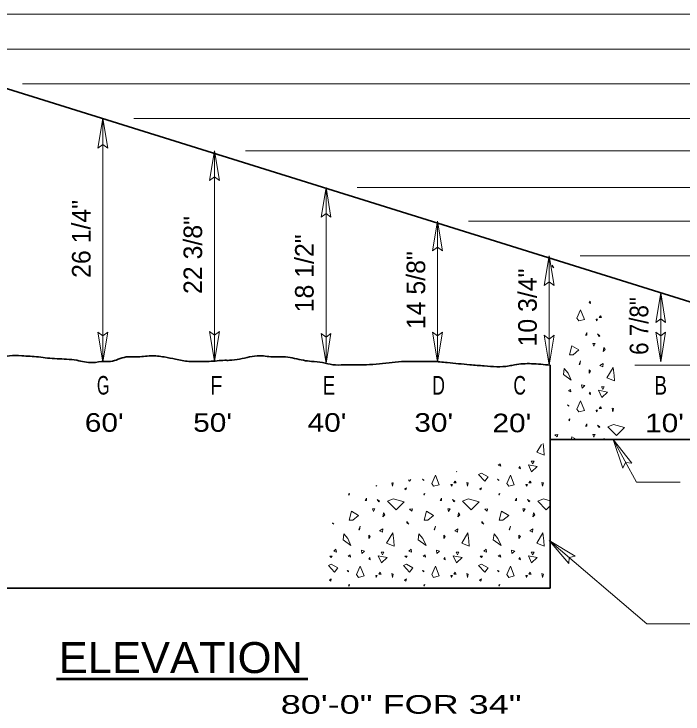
# Model space of a CAD drawing. Extents: x -15.1 to -7.9, y 13.6 to 23.8.
# Drawn here: x -13.723 to -11.564, y 19.638 to 21.898 of the extents above; entities that cross this region are included whole.
import ezdxf
from ezdxf.enums import TextEntityAlignment as Align

# ---------------------------------------------------------------- set-up
doc = ezdxf.new("R2010")
doc.units = 0
doc.header["$LTSCALE"] = 0.024
for name, color, linetype, lineweight in [('1', 7, 'Continuous', 35), ('10', 7, 'Continuous', 13), ('12', 7, 'Continuous', 53), ('6', 7, 'Continuous', 13)]:
    doc.layers.add(name, color=color, linetype=linetype, lineweight=lineweight)

msp = doc.modelspace()

# ---------------------------------------------------------------- linework, layer by layer
at = {"layer": '1'}
for p, q in [((-14.51633, 21.89767), (-11.27283, 20.88417)), ((-11.993, 20.044), (-11.993, 20.7645)), ((-11.993, 20.044), (-14.91633, 20.044))]:
    msp.add_line(p, q, dxfattribs=at)
msp.add_lwpolyline([(-11.993, 20.524), (-11.27283, 20.524), (-11.27283, 20.88417)], dxfattribs=at)
msp.add_spline([(-11.993, 20.76417), (-12.053, 20.769), (-12.1075, 20.7655), (-12.1255, 20.76183), (-12.20533, 20.76183), (-12.25233, 20.7655), (-12.32483, 20.77267), (-12.372, 20.77633), (-12.41917, 20.77633), (-12.46267, 20.77633), (-12.5025, 20.77267), (-12.58583, 20.7655), (-12.6185, 20.7655), (-12.65833, 20.7655), (-12.6945, 20.7655), (-12.72717, 20.77267), (-12.7635, 20.77633), (-12.78883, 20.77983), (-12.84683, 20.79067), (-12.883, 20.79067), (-12.93017, 20.79433), (-12.96283, 20.79067), (-13.028, 20.77983), (-13.0425, 20.77983), (-13.09317, 20.77633), (-13.11867, 20.77633), (-13.1585, 20.77633), (-13.202, 20.7835), (-13.23817, 20.79067), (-13.28167, 20.79433), (-13.32883, 20.79067), (-13.3615, 20.79067), (-13.41217, 20.77633), (-13.43033, 20.77633), (-13.47017, 20.77267), (-13.52083, 20.77983), (-13.5535, 20.7835), (-13.61517, 20.78717), (-13.64417, 20.79067), (-13.6985, 20.79433), (-13.73833, 20.79433), (-13.8, 20.77983), (-13.81083, 20.77983), (-13.84717, 20.77983), (-13.90517, 20.7835), (-13.974, 20.7835), (-14.01383, 20.77983), (-14.05733, 20.769), (-14.0935, 20.75817), (-14.108, 20.75467), (-14.14067, 20.75467), (-14.17333, 20.75467), (-14.23483, 20.76183), (-14.27483, 20.76183), (-14.31833, 20.75817), (-14.34717, 20.75467), (-14.369, 20.75467), (-14.40883, 20.75467), (-14.43783, 20.75817), (-14.456, 20.7655), (-14.46683, 20.769), (-14.48867, 20.77633), (-14.50317, 20.77633), (-14.51033, 20.77633)], degree=3, dxfattribs=at)
at = {"layer": '10'}
for p, q in [((-14.41633, 21.89767), (-9.09375, 21.89767)), ((-14.05633, 21.78433), (-9.13367, 21.78433)), ((-13.69633, 21.67267), (-9.14125, 21.67267)), ((-13.45233, 21.46417), (-13.43633, 21.56017)), ((-13.43633, 20.775), (-13.43633, 21.56017)), ((-13.42033, 21.46417), (-13.43633, 21.56017)), ((-13.33633, 21.56017), (-9.14125, 21.56017)), ((-13.45233, 21.46417), (-13.43633, 21.47617)), ((-13.42033, 21.46417), (-13.43633, 21.47617)), ((-13.09217, 21.36017), (-13.07617, 21.45617)), ((-13.06017, 21.36017), (-13.07617, 21.45617)), ((-13.07617, 20.777), (-13.07617, 21.45617)), ((-12.97617, 21.45617), (-9.14125, 21.45617)), ((-13.09217, 21.36017), (-13.07617, 21.37217)), ((-13.06017, 21.36017), (-13.07617, 21.37217)), ((-12.73217, 21.24167), (-12.71617, 21.33767)), ((-12.70017, 21.24167), (-12.71617, 21.33767)), ((-12.71617, 20.77017), (-12.71617, 21.33767)), ((-12.61617, 21.33767), (-9.14883, 21.33767)), ((-12.73217, 21.24167), (-12.71617, 21.25367)), ((-12.70017, 21.24167), (-12.71617, 21.25367)), ((-12.37217, 21.133), (-12.35617, 21.22917)), ((-12.35617, 20.775), (-12.35617, 21.22917)), ((-12.34017, 21.133), (-12.35617, 21.22917)), ((-12.25617, 21.22917), (-9.16858, 21.22917)), ((-12.37217, 21.133), (-12.35617, 21.145)), ((-12.34017, 21.133), (-12.35617, 21.145)), ((-12.012, 21.02117), (-11.996, 21.11717)), ((-11.98, 21.02117), (-11.996, 21.11717)), ((-11.996, 20.7645), (-11.996, 21.11717)), ((-11.896, 21.11717), (-9.21133, 21.11717)), ((-12.012, 21.02117), (-11.996, 21.03317)), ((-11.98, 21.02117), (-11.996, 21.03317)), ((-11.652, 20.90167), (-11.636, 20.99767)), ((-11.636, 20.775), (-11.636, 20.99767)), ((-11.62, 20.90167), (-11.636, 20.99767)), ((-11.652, 20.90167), (-11.636, 20.91367)), ((-11.62, 20.90167), (-11.636, 20.91367)), ((-13.45233, 20.871), (-13.43633, 20.775)), ((-13.45233, 20.871), (-13.43633, 20.859)), ((-13.42033, 20.871), (-13.43633, 20.775)), ((-13.42033, 20.871), (-13.43633, 20.859)), ((-13.09217, 20.873), (-13.07617, 20.777)), ((-13.09217, 20.873), (-13.07617, 20.861)), ((-13.06017, 20.873), (-13.07617, 20.777)), ((-13.06017, 20.873), (-13.07617, 20.861)), ((-12.73217, 20.86617), (-12.71617, 20.77017)), ((-12.73217, 20.86617), (-12.71617, 20.85417)), ((-12.70017, 20.86617), (-12.71617, 20.77017)), ((-12.70017, 20.86617), (-12.71617, 20.85417)), ((-12.37217, 20.871), (-12.35617, 20.775)), ((-12.37217, 20.871), (-12.35617, 20.859)), ((-12.34017, 20.871), (-12.35617, 20.775)), ((-12.34017, 20.871), (-12.35617, 20.859)), ((-12.012, 20.86067), (-11.996, 20.7645)), ((-12.012, 20.86067), (-11.996, 20.84867)), ((-11.98, 20.86067), (-11.996, 20.7645)), ((-11.98, 20.86067), (-11.996, 20.84867)), ((-11.652, 20.871), (-11.636, 20.775)), ((-11.652, 20.871), (-11.636, 20.859)), ((-11.62, 20.871), (-11.636, 20.775)), ((-11.62, 20.871), (-11.636, 20.859)), ((-9.52933, 20.7645), (-11.71933, 20.7645)), ((-11.75767, 20.43217), (-11.78983, 20.524)), ((-11.7295, 20.44767), (-11.78983, 20.524)), ((-11.71433, 20.38667), (-11.78983, 20.524)), ((-11.75767, 20.43217), (-11.74933, 20.4505)), ((-11.7295, 20.44767), (-11.74933, 20.4505)), ((-11.57317, 20.38667), (-11.71433, 20.38667)), ((-11.681, 19.92983), (-11.9955, 20.19833)), ((-11.933, 20.12383), (-11.9955, 20.19833)), ((-11.91217, 20.14817), (-11.9955, 20.19833)), ((-11.933, 20.12383), (-11.93167, 20.14383)), ((-11.91217, 20.14817), (-11.93167, 20.14383)), ((-11.681, 19.92983), (-11.39683, 19.92983))]:
    msp.add_line(p, q, dxfattribs=at)
at = {"layer": '12'}
msp.add_line((-13.586, 19.75183), (-12.77517, 19.75183), dxfattribs=at)
at = {"layer": '6'}
for points in [[(-11.9865, 21.08733), (-11.9865, 21.08267), (-11.9805, 21.07833)], [(-11.867, 20.966), (-11.86233, 20.96317), (-11.86383, 20.97067)], [(-11.90017, 20.907), (-11.88217, 20.91167), (-11.89433, 20.94333), (-11.90633, 20.91633)], [(-11.83067, 20.92383), (-11.8275, 20.91767), (-11.835, 20.91767)], [(-11.84433, 20.913), (-11.84283, 20.907), (-11.83967, 20.913)], [(-11.87467, 20.86917), (-11.879, 20.8615), (-11.87467, 20.8615)], [(-11.835, 20.85717), (-11.83217, 20.85867), (-11.83967, 20.86483)], [(-11.85483, 20.83417), (-11.852, 20.82517), (-11.84717, 20.83417)], [(-11.9185, 20.79783), (-11.90017, 20.81333), (-11.92283, 20.82667), (-11.93033, 20.79783)], [(-11.81983, 20.82083), (-11.82167, 20.80867), (-11.8155, 20.81467)], [(-11.89867, 20.76617), (-11.89733, 20.76617), (-11.89433, 20.77833)], [(-11.83217, 20.76333), (-11.82317, 20.7585), (-11.82167, 20.76933)], [(-11.94733, 20.75383), (-11.95017, 20.7345), (-11.92467, 20.71617), (-11.93517, 20.73883)], [(-11.867, 20.7495), (-11.867, 20.73883), (-11.86233, 20.74483)], [(-11.78667, 20.73117), (-11.78533, 20.71317), (-11.8095, 20.72367), (-11.78967, 20.75717)], [(-11.89117, 20.701), (-11.88967, 20.6905), (-11.88067, 20.69817)], [(-11.93367, 20.6815), (-11.92617, 20.67833), (-11.9275, 20.68583)], [(-11.867, 20.67217), (-11.86233, 20.66933), (-11.86383, 20.67683)], [(-11.83683, 20.683), (-11.826, 20.66033), (-11.808, 20.67683)], [(-11.8275, 20.69483), (-11.82317, 20.68583), (-11.8185, 20.69483)], [(-11.93217, 20.63433), (-11.9365, 20.63583), (-11.93217, 20.6315)], [(-11.90017, 20.61317), (-11.88217, 20.61783), (-11.89433, 20.6495), (-11.90633, 20.6225)], [(-11.83067, 20.63), (-11.8275, 20.624), (-11.835, 20.624)], [(-11.84433, 20.61917), (-11.84283, 20.61317), (-11.83967, 20.61917)], [(-11.79283, 20.62533), (-11.791, 20.61317), (-11.78817, 20.624)], [(-11.929, 20.5905), (-11.93217, 20.5875), (-11.93033, 20.58433)], [(-11.87467, 20.57533), (-11.879, 20.56767), (-11.87467, 20.56767)], [(-11.835, 20.5635), (-11.83217, 20.56483), (-11.83967, 20.571)], [(-11.78817, 20.5725), (-11.75333, 20.5635), (-11.77917, 20.5375), (-11.8065, 20.56483)], [(-11.9775, 20.539), (-11.97, 20.53283), (-11.9685, 20.54033)], [(-11.85483, 20.54033), (-11.852, 20.53133), (-11.84717, 20.54033)], [(-12.05383, 20.45483), (-12.0495, 20.44583), (-12.04483, 20.45483)], [(-12.0935, 20.43217), (-12.08883, 20.42933), (-12.09017, 20.43683)], [(-12.06317, 20.443), (-12.0525, 20.42033), (-12.0345, 20.43683)], [(-12.22383, 20.41133), (-12.204, 20.39), (-12.19317, 20.40333), (-12.2145, 20.41567)], [(-12.12667, 20.37317), (-12.10867, 20.37783), (-12.12083, 20.4095), (-12.13267, 20.3825)], [(-12.401, 20.39433), (-12.40533, 20.39583), (-12.401, 20.3915)], [(-12.2995, 20.39), (-12.29617, 20.384), (-12.30383, 20.384)], [(-12.26167, 20.38533), (-12.25983, 20.37317), (-12.257, 20.384)], [(-12.15867, 20.39433), (-12.163, 20.39583), (-12.15867, 20.3915)], [(-12.05717, 20.39), (-12.05383, 20.384), (-12.0615, 20.384)], [(-12.01933, 20.38533), (-12.0175, 20.37317), (-12.01467, 20.384)], [(-12.46283, 20.36417), (-12.4585, 20.36133), (-12.45683, 20.36883)], [(-12.31317, 20.37933), (-12.31167, 20.37317), (-12.3085, 20.37933)], [(-12.2205, 20.36417), (-12.21633, 20.36133), (-12.2145, 20.36883)], [(-12.07083, 20.37933), (-12.06933, 20.37317), (-12.06617, 20.37933)], [(-12.64, 20.3505), (-12.64333, 20.34767), (-12.6415, 20.34433)], [(-12.58567, 20.33533), (-12.59, 20.32783), (-12.58567, 20.32783)], [(-12.39767, 20.3505), (-12.401, 20.34767), (-12.39917, 20.34433)], [(-12.34333, 20.33533), (-12.34767, 20.32783), (-12.34333, 20.32783)], [(-12.15533, 20.3505), (-12.15867, 20.34767), (-12.15683, 20.34433)], [(-12.101, 20.33533), (-12.10533, 20.32783), (-12.101, 20.32783)], [(-12.546, 20.3235), (-12.54317, 20.32483), (-12.55067, 20.331)], [(-12.49933, 20.3325), (-12.46433, 20.3235), (-12.49033, 20.2975), (-12.51767, 20.32483)], [(-12.30383, 20.3235), (-12.30083, 20.32483), (-12.3085, 20.331)], [(-12.257, 20.3325), (-12.222, 20.3235), (-12.248, 20.2975), (-12.27533, 20.32483)], [(-12.0615, 20.3235), (-12.0585, 20.32483), (-12.06617, 20.331)], [(-12.62967, 20.264), (-12.61117, 20.2795), (-12.634, 20.29283), (-12.6415, 20.264)], [(-12.56583, 20.3005), (-12.563, 20.2915), (-12.55833, 20.3005)], [(-12.44633, 20.299), (-12.43883, 20.29283), (-12.43733, 20.3005)], [(-12.38733, 20.264), (-12.369, 20.2795), (-12.39167, 20.29283), (-12.39917, 20.264)], [(-12.3235, 20.3005), (-12.32067, 20.2915), (-12.316, 20.3005)], [(-12.204, 20.299), (-12.1965, 20.29283), (-12.195, 20.3005)], [(-12.145, 20.264), (-12.12667, 20.2795), (-12.14933, 20.29283), (-12.15683, 20.264)], [(-12.08117, 20.3005), (-12.07833, 20.2915), (-12.07367, 20.3005)], [(-12.531, 20.28717), (-12.53267, 20.27483), (-12.52667, 20.281)], [(-12.28867, 20.28717), (-12.2905, 20.27483), (-12.28433, 20.281)], [(-12.04633, 20.28717), (-12.04817, 20.27483), (-12.042, 20.281)], [(-12.60983, 20.23233), (-12.60833, 20.23233), (-12.6055, 20.24467)], [(-12.45533, 20.25967), (-12.45533, 20.255), (-12.44917, 20.25067)], [(-12.3675, 20.23233), (-12.366, 20.23233), (-12.36317, 20.24467)], [(-12.213, 20.25967), (-12.213, 20.255), (-12.20683, 20.25067)], [(-12.12517, 20.23233), (-12.12367, 20.23233), (-12.12083, 20.24467)], [(-12.54317, 20.2295), (-12.53417, 20.22483), (-12.53267, 20.23567)], [(-12.49783, 20.1975), (-12.49633, 20.1795), (-12.5205, 20.18983), (-12.50067, 20.22333)], [(-12.30083, 20.2295), (-12.29183, 20.22483), (-12.2905, 20.23567)], [(-12.2555, 20.1975), (-12.254, 20.1795), (-12.27817, 20.18983), (-12.25833, 20.22333)], [(-12.0585, 20.2295), (-12.0495, 20.22483), (-12.04817, 20.23567)], [(-12.01317, 20.1975), (-12.01167, 20.1795), (-12.03583, 20.18983), (-12.016, 20.22333)], [(-12.65833, 20.22017), (-12.66133, 20.20067), (-12.63567, 20.18233), (-12.64617, 20.205)], [(-12.57817, 20.21583), (-12.57817, 20.205), (-12.5735, 20.21117)], [(-12.41617, 20.22017), (-12.419, 20.20067), (-12.39333, 20.18233), (-12.40383, 20.205)], [(-12.33583, 20.21583), (-12.33583, 20.205), (-12.33117, 20.21117)], [(-12.17383, 20.22017), (-12.17667, 20.20067), (-12.15117, 20.18233), (-12.1615, 20.205)], [(-12.0935, 20.21583), (-12.0935, 20.205), (-12.08883, 20.21117)], [(-12.684, 20.1705), (-12.6915, 20.16433), (-12.6825, 20.16117)], [(-12.60217, 20.16717), (-12.60083, 20.15683), (-12.59183, 20.16433)], [(-12.5385, 20.16117), (-12.53417, 20.152), (-12.5295, 20.16117)], [(-12.44167, 20.1705), (-12.44917, 20.16433), (-12.44017, 20.16117)], [(-12.36, 20.16717), (-12.3585, 20.15683), (-12.3495, 20.16433)], [(-12.29617, 20.16117), (-12.29183, 20.152), (-12.28717, 20.16117)], [(-12.19933, 20.1705), (-12.20683, 20.16433), (-12.19783, 20.16117)], [(-12.11767, 20.16717), (-12.11617, 20.15683), (-12.10717, 20.16433)], [(-12.05383, 20.16117), (-12.0495, 20.152), (-12.04483, 20.16117)], [(-12.70383, 20.14783), (-12.69917, 20.143), (-12.69617, 20.14783)], [(-12.64467, 20.14783), (-12.63717, 20.1445), (-12.63867, 20.152)], [(-12.57817, 20.13833), (-12.5735, 20.1355), (-12.57483, 20.143)], [(-12.54783, 20.14917), (-12.537, 20.1265), (-12.519, 20.143)], [(-12.4615, 20.14783), (-12.45683, 20.143), (-12.45383, 20.14783)], [(-12.40233, 20.14783), (-12.39483, 20.1445), (-12.39633, 20.152)], [(-12.33583, 20.13833), (-12.33117, 20.1355), (-12.3325, 20.143)], [(-12.3055, 20.14917), (-12.29467, 20.1265), (-12.27667, 20.143)], [(-12.21917, 20.14783), (-12.2145, 20.143), (-12.2115, 20.14783)], [(-12.16017, 20.14783), (-12.1525, 20.1445), (-12.154, 20.152)], [(-12.0935, 20.13833), (-12.08883, 20.1355), (-12.09017, 20.143)], [(-12.06317, 20.14917), (-12.0525, 20.1265), (-12.0345, 20.143)], [(-12.7085, 20.1175), (-12.68867, 20.09633), (-12.67783, 20.10967), (-12.69917, 20.12183)], [(-12.61117, 20.07933), (-12.59317, 20.084), (-12.6055, 20.11567), (-12.61733, 20.08867)], [(-12.46617, 20.1175), (-12.44633, 20.09633), (-12.4355, 20.10967), (-12.45683, 20.12183)], [(-12.369, 20.07933), (-12.351, 20.084), (-12.36317, 20.11567), (-12.375, 20.08867)], [(-12.22383, 20.1175), (-12.204, 20.09633), (-12.19317, 20.10967), (-12.2145, 20.12183)], [(-12.12667, 20.07933), (-12.10867, 20.084), (-12.12083, 20.11567), (-12.13267, 20.08867)], [(-12.64333, 20.10067), (-12.64767, 20.102), (-12.64333, 20.09767)], [(-12.54167, 20.09633), (-12.5385, 20.09017), (-12.546, 20.09017)], [(-12.504, 20.09167), (-12.50217, 20.07933), (-12.49933, 20.09017)], [(-12.401, 20.10067), (-12.40533, 20.102), (-12.401, 20.09767)], [(-12.2995, 20.09633), (-12.29617, 20.09017), (-12.30383, 20.09017)], [(-12.26167, 20.09167), (-12.25983, 20.07933), (-12.257, 20.09017)], [(-12.15867, 20.10067), (-12.163, 20.102), (-12.15867, 20.09767)], [(-12.05717, 20.09633), (-12.05383, 20.09017), (-12.0615, 20.09017)], [(-12.01933, 20.09167), (-12.0175, 20.07933), (-12.01467, 20.09017)], [(-12.70517, 20.07033), (-12.70083, 20.0675), (-12.69917, 20.075)], [(-12.5555, 20.0855), (-12.554, 20.07933), (-12.55067, 20.0855)], [(-12.46283, 20.07033), (-12.4585, 20.0675), (-12.45683, 20.075)], [(-12.31317, 20.0855), (-12.31167, 20.07933), (-12.3085, 20.0855)], [(-12.2205, 20.07033), (-12.21633, 20.0675), (-12.2145, 20.075)], [(-12.07083, 20.0855), (-12.06933, 20.07933), (-12.06617, 20.0855)], [(-12.64, 20.05667), (-12.64333, 20.05383), (-12.6415, 20.0505)], [(-12.39767, 20.05667), (-12.401, 20.05383), (-12.39917, 20.0505)], [(-12.15533, 20.05667), (-12.15867, 20.05383), (-12.15683, 20.0505)]]:
    msp.add_lwpolyline(points, close=True, dxfattribs=at)
for points in [[(-11.908, 20.524), (-11.92283, 20.53283), (-11.92517, 20.524)], [(-11.81783, 20.524), (-11.81983, 20.527), (-11.82033, 20.524)], [(-12.0155, 20.51167), (-12.01317, 20.49133), (-12.01167, 20.47333), (-12.03583, 20.48367), (-12.02117, 20.50867)], [(-12.15433, 20.44567), (-12.16017, 20.4415), (-12.1525, 20.43833), (-12.154, 20.44567)], [(-12.36333, 20.409), (-12.375, 20.3825), (-12.369, 20.37317), (-12.351, 20.37783), (-12.363, 20.40917)], [(-12.295, 20.421), (-12.29467, 20.42033), (-12.29383, 20.42117)], [(-12.50383, 20.3845), (-12.50217, 20.37317), (-12.49933, 20.384), (-12.502, 20.38483)], [(-12.44983, 20.394), (-12.44633, 20.39), (-12.44217, 20.39517)], [(-12.5545, 20.37567), (-12.554, 20.37317), (-12.5525, 20.376)], [(-11.993, 20.31017), (-12.00567, 20.2975), (-12.033, 20.32483), (-12.01467, 20.3325), (-11.993, 20.32683)], [(-12.69583, 20.25383), (-12.6915, 20.25067), (-12.69483, 20.25567)]]:
    msp.add_lwpolyline(points, dxfattribs=at)

# ---------------------------------------------------------------- texts
at = {"layer": '12'}
for s, p in [('26 1/4"', (-13.47625, 21.17167)), ('22 3/8"', (-13.11617, 21.11967)), ('18 1/2"', (-12.75617, 21.0605)), ('14 5/8"', (-12.39608, 21.00617)), ('10 3/4"', (-12.036, 20.95025))]:
    msp.add_text(s, height=0.06001, rotation=90, dxfattribs=at).set_placement(p, align=Align.CENTER)
at = {"layer": '12', "width": 0.9}
msp.add_text('6 7/8"', height=0.06001, rotation=90, dxfattribs=at).set_placement((-11.676, 20.8905), align=Align.CENTER)
at = {"layer": '12'}
for s, width, p in [('G', 0.65, (-13.45567, 20.66925)), ('F', 0.8, (-13.08958, 20.66925)), ('E', 0.75, (-12.72658, 20.66925)), ('D', 0.7, (-12.37292, 20.66925)), ('C', 0.7, (-12.11142, 20.66925)), ('B', 0.75, (-11.65583, 20.66925)), ("60'", 1.2, (-13.49475, 20.54925)), ("50'", 1.2, (-13.145, 20.54925)), ("40'", 1.2, (-12.77583, 20.54925)), ("30'", 1.2, (-12.43133, 20.54925)), ("20'", 1.2, (-12.17908, 20.54767)), ("10'", 1.2, (-11.6865, 20.54767))]:
    msp.add_text(s, height=0.06001, dxfattribs=dict(at, width=width)).set_placement(p)
for s, height, width, p in [('ELEVATION', 0.1, 1.05, (-13.18487, 19.77042)), ('80\'-0" FOR 34"', 0.06, 1.45, (-12.47375, 19.63917))]:
    msp.add_text(s, height=height, dxfattribs=dict(at, width=width)).set_placement(p, align=Align.CENTER)

doc.saveas('drawing.dxf')
